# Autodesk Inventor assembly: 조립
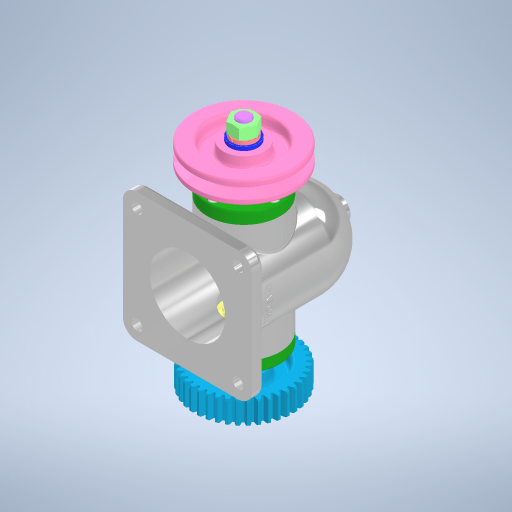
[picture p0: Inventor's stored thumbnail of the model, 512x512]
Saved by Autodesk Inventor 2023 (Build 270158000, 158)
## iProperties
Created: 2025-04
Part Number: 조립
Document SubType Name: Assembly
Designer: ADMIN_PC
Author: ADMIN_PC
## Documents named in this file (14)
- C:\Users\ADMIN_PC\Desktop\인벤터\답안조립.iam
- C:\Users\ADMIN_PC\Desktop\인벤터\답안본체.ipt
- C:\Users\ADMIN_PC\Desktop\인벤터\부품\6각 구멍붙이 볼트 M4x12.ipt
- C:\Users\ADMIN_PC\Desktop\인벤터\부품\깊은 홈 볼 베어링 6203.ipt
- C:\Users\ADMIN_PC\Desktop\인벤터\부품\커버.ipt
- C:\Users\ADMIN_PC\Desktop\인벤터\부품\축.ipt
- C:\Users\ADMIN_PC\Desktop\인벤터\부품\오일 실 26 38 8.ipt
- C:\Users\ADMIN_PC\Desktop\인벤터\부품\칼라.ipt
- C:\Users\ADMIN_PC\Desktop\인벤터\부품\평행 키 5x5x12.ipt
- C:\Users\ADMIN_PC\Desktop\인벤터\부품\스퍼기어.ipt
- C:\Users\ADMIN_PC\Desktop\인벤터\부품\V 벨트 풀리.ipt
- C:\Users\ADMIN_PC\Desktop\인벤터\부품\평와셔 M12.ipt
- C:\Users\ADMIN_PC\Desktop\인벤터\부품\스프링 와셔 M12.ipt
- C:\Users\ADMIN_PC\Desktop\인벤터\부품\6각 너트 M12x1.ipt
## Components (11 placed, 3 different names)
1. 6각 구멍붙이 볼트 M4x12:1
2. 6각 구멍붙이 볼트 M4x12:2
3. 6각 구멍붙이 볼트 M4x12:3
4. 6각 구멍붙이 볼트 M4x12:4
5. 6각 구멍붙이 볼트 M4x12:5
6. 6각 구멍붙이 볼트 M4x12:6
7. 6각 구멍붙이 볼트 M4x12:7
8. 6각 구멍붙이 볼트 M4x12:8
9. V 벨트 풀리:1
10. 6각 너트 M12x1:1
11. 6각 너트 M12x1:2
